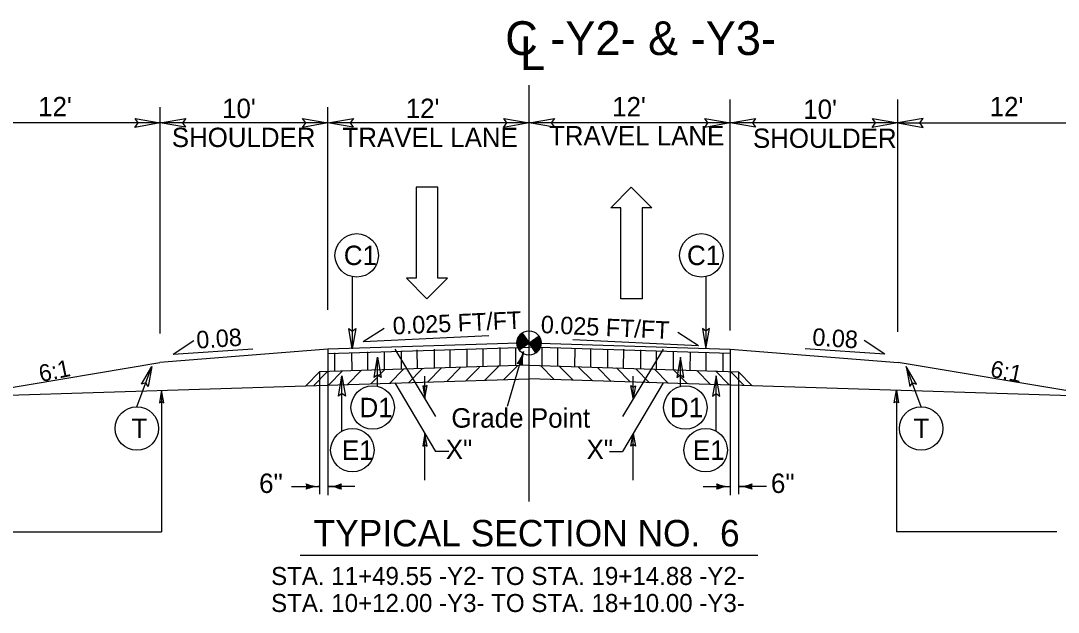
# Model space of a CAD drawing. Extents: x 2176156 to 2177167, y 76401 to 76644.
# Drawn here: x 2176967.8 to 2177029.7, y 76459.2 to 76494.4 of the extents above; entities that cross this region are included whole.
import ezdxf

# ---------------------------------------------------------------- set-up
doc = ezdxf.new("R2010")
doc.units = 0
for name, color, linetype in [('Exist Building', 7, 'Continuous'), ('Exist Building Metal Canopy', 7, 'Continuous'), ('Exist Roads Change in Surface', 7, 'Continuous'), ('Exist Roads Curbs', 7, 'Continuous'), ('Exist Roads EOP Other', 7, 'Continuous'), ('Exist Roads Soil', 7, 'Continuous'), ('Exist Structure Minor Culvert Topo', 7, 'Continuous'), ('Exist Structure Minor Drop Inlet', 7, 'Continuous'), ('Exist Utilities Other Pole CELL', 7, 'Continuous'), ('Exist Vegetation Woods Line', 7, 'Continuous'), ('Model Boundary Lines Text', 7, 'Continuous'), ('Old_Level_1', 7, 'Continuous'), ('Old_Level_3', 7, 'Continuous'), ('Prop North Arrow NAD83 for Plan Sheets CELL', 7, 'Continuous')]:
    doc.layers.add(name, color=color, linetype=linetype)

msp = doc.modelspace()

# ---------------------------------------------------------------- linework, layer by layer
at = {"layer": 'Exist Building'}
for p, q in [((2176998.106, 76473.085), (2176998.106, 76475.223)), ((2176998.106, 76473.085), (2176998.106, 76475.223)), ((2176963.901, 76472.018), (2176998.106, 76473.085)), ((2177032.311, 76472.018), (2176998.106, 76473.085))]:
    msp.add_line(p, q, dxfattribs=at)
at = {"layer": 'Exist Roads Change in Surface'}
for p, q in [((2176997.694, 76475.815), (2176998.106, 76475.223)), ((2176998.106, 76475.223), (2176998.698, 76475.635)), ((2176997.513, 76474.813), (2176998.106, 76475.223)), ((2176998.106, 76475.223), (2176997.513, 76474.813)), ((2176998.518, 76474.632), (2176998.106, 76475.223))]:
    msp.add_line(p, q, dxfattribs=at)
for points in [[(2176997.82, 76475.635), (2176997.394, 76475.338)], [(2176997.811, 76475.647), (2176997.397, 76475.359)], [(2176997.803, 76475.659), (2176997.402, 76475.38)], [(2176997.795, 76475.67), (2176997.407, 76475.401)], [(2176997.787, 76475.682), (2176997.413, 76475.422)], [(2176997.779, 76475.694), (2176997.42, 76475.444)], [(2176997.77, 76475.706), (2176997.427, 76475.467)], [(2176997.762, 76475.718), (2176997.436, 76475.491)], [(2176997.754, 76475.73), (2176997.446, 76475.515)], [(2176997.746, 76475.741), (2176997.459, 76475.542)], [(2176997.737, 76475.753), (2176997.473, 76475.569)], [(2176997.729, 76475.765), (2176997.49, 76475.599)], [(2176997.721, 76475.777), (2176997.509, 76475.63)], [(2176997.713, 76475.789), (2176997.536, 76475.666)], [(2176997.704, 76475.801), (2176997.57, 76475.707)], [(2176997.696, 76475.812), (2176997.632, 76475.768)], [(2176998.701, 76475.63), (2176998.701, 76475.63), (2176998.11, 76475.218)], [(2176997.861, 76475.576), (2176997.385, 76475.244)], [(2176997.869, 76475.564), (2176997.385, 76475.227)], [(2176997.853, 76475.588), (2176997.386, 76475.263)], [(2176997.877, 76475.552), (2176997.386, 76475.21)], [(2176997.886, 76475.54), (2176997.386, 76475.193)], [(2176997.894, 76475.528), (2176997.386, 76475.175)], [(2176997.844, 76475.599), (2176997.387, 76475.281)], [(2176997.902, 76475.517), (2176997.388, 76475.159)], [(2176997.836, 76475.611), (2176997.389, 76475.3)], [(2176997.91, 76475.505), (2176997.39, 76475.142)], [(2176997.828, 76475.623), (2176997.391, 76475.319)], [(2176997.918, 76475.493), (2176997.391, 76475.126)], [(2176997.927, 76475.481), (2176997.394, 76475.11)], [(2176997.935, 76475.469), (2176997.397, 76475.095)], [(2176997.943, 76475.457), (2176997.4, 76475.079)], [(2176997.951, 76475.446), (2176997.403, 76475.064)], [(2176997.96, 76475.434), (2176997.406, 76475.049)], [(2176997.968, 76475.422), (2176997.41, 76475.034)], [(2176997.976, 76475.41), (2176997.415, 76475.019)], [(2176997.984, 76475.398), (2176997.419, 76475.005)], [(2176997.993, 76475.386), (2176997.425, 76474.991)], [(2176998.001, 76475.375), (2176997.429, 76474.977)], [(2176998.009, 76475.363), (2176997.435, 76474.963)], [(2176998.017, 76475.351), (2176997.44, 76474.949)], [(2176998.026, 76475.339), (2176997.446, 76474.936)], [(2176998.034, 76475.327), (2176997.451, 76474.922)], [(2176998.042, 76475.315), (2176997.458, 76474.909)], [(2176998.05, 76475.304), (2176997.464, 76474.896)], [(2176998.058, 76475.292), (2176997.471, 76474.883)], [(2176998.067, 76475.28), (2176997.478, 76474.87)], [(2176998.075, 76475.268), (2176997.485, 76474.857)], [(2176998.083, 76475.256), (2176997.493, 76474.845)], [(2176998.091, 76475.244), (2176997.5, 76474.833)], [(2176998.1, 76475.233), (2176997.508, 76474.821), (2176997.508, 76474.821)], [(2176998.71, 76475.618), (2176998.118, 76475.206)], [(2176998.717, 76475.605), (2176998.126, 76475.194)], [(2176998.725, 76475.593), (2176998.134, 76475.183)], [(2176998.732, 76475.581), (2176998.143, 76475.171)], [(2176998.739, 76475.568), (2176998.151, 76475.159)], [(2176998.746, 76475.555), (2176998.159, 76475.147)], [(2176998.752, 76475.542), (2176998.167, 76475.135)], [(2176998.759, 76475.53), (2176998.176, 76475.123)], [(2176998.765, 76475.516), (2176998.184, 76475.112)], [(2176998.771, 76475.502), (2176998.192, 76475.1)], [(2176998.776, 76475.489), (2176998.2, 76475.088)], [(2176998.782, 76475.475), (2176998.209, 76475.076)], [(2176998.786, 76475.461), (2176998.217, 76475.064)], [(2176998.792, 76475.447), (2176998.225, 76475.052)], [(2176998.796, 76475.432), (2176998.233, 76475.041)], [(2176998.8, 76475.418), (2176998.241, 76475.029)], [(2176998.805, 76475.403), (2176998.25, 76475.017)], [(2176998.808, 76475.388), (2176998.258, 76475.005)], [(2176998.811, 76475.372), (2176998.266, 76474.993)], [(2176998.813, 76475.357), (2176998.274, 76474.981)], [(2176998.817, 76475.341), (2176998.283, 76474.97)], [(2176998.82, 76475.326), (2176998.291, 76474.958)], [(2176998.821, 76475.309), (2176998.299, 76474.946)], [(2176998.823, 76475.293), (2176998.307, 76474.934)], [(2176998.824, 76475.276), (2176998.316, 76474.922)], [(2176998.826, 76475.26), (2176998.324, 76474.91)], [(2176998.826, 76475.243), (2176998.332, 76474.899)], [(2176998.827, 76475.225), (2176998.34, 76474.887)], [(2176998.826, 76475.207), (2176998.349, 76474.875)], [(2176998.826, 76475.19), (2176998.357, 76474.863)], [(2176998.825, 76475.171), (2176998.365, 76474.851)], [(2176998.823, 76475.152), (2176998.373, 76474.839)], [(2176998.821, 76475.133), (2176998.381, 76474.828)], [(2176998.818, 76475.114), (2176998.39, 76474.816)], [(2176998.815, 76475.094), (2176998.398, 76474.804)], [(2176998.811, 76475.074), (2176998.406, 76474.792)], [(2176998.806, 76475.053), (2176998.414, 76474.78)], [(2176998.8, 76475.031), (2176998.423, 76474.768)], [(2176998.794, 76475.009), (2176998.431, 76474.757)], [(2176998.786, 76474.986), (2176998.439, 76474.745)], [(2176998.777, 76474.963), (2176998.447, 76474.733)], [(2176998.767, 76474.938), (2176998.456, 76474.721)], [(2176998.756, 76474.912), (2176998.464, 76474.709)], [(2176998.743, 76474.886), (2176998.472, 76474.697)], [(2176998.726, 76474.857), (2176998.48, 76474.686)], [(2176998.707, 76474.826), (2176998.489, 76474.674)], [(2176998.682, 76474.791), (2176998.497, 76474.662)], [(2176998.65, 76474.751), (2176998.505, 76474.65)], [(2176998.597, 76474.697), (2176998.513, 76474.638)]]:
    msp.add_lwpolyline(points, dxfattribs=at)
msp.add_circle((2176998.106, 76475.224), 0.721, dxfattribs=at)
for start, end in [(124.8249, 214.8249), (304.8249, 34.8249)]:
    msp.add_arc((2176998.106, 76475.224), 0.721, start, end, dxfattribs=at)
at = {"layer": 'Exist Roads Curbs'}
for points in [[(2176998.105, 76475.223), (2176998.106, 76475.223), (2176986.106, 76474.849), (2176986.106, 76474.599), (2176998.106, 76474.973), (2176998.106, 76474.973)], [(2176998.107, 76475.223), (2176998.106, 76475.223), (2177010.106, 76474.849), (2177010.106, 76474.599), (2176998.106, 76474.973), (2176998.106, 76474.973)]]:
    msp.add_lwpolyline(points, close=True, dxfattribs=at)
at = {"layer": 'Exist Roads EOP Other'}
for p, q in [((2176986.106, 76474.849), (2176976.071, 76474.046)), ((2177010.106, 76474.849), (2177020.141, 76474.046))]:
    msp.add_line(p, q, dxfattribs=at)
at = {"layer": 'Exist Roads Soil'}
for p, q in [((2176986.106, 76474.849), (2176986.106, 76473.517)), ((2177010.106, 76474.849), (2177010.106, 76473.517)), ((2176948.119, 76469.388), (2176976.071, 76474.046)), ((2176998.106, 76473.891), (2176985.602, 76473.501)), ((2176998.106, 76473.891), (2177010.61, 76473.501)), ((2177048.093, 76469.388), (2177020.141, 76474.046)), ((2176985.602, 76473.501), (2176984.793, 76472.669)), ((2177010.61, 76473.501), (2177011.419, 76472.669))]:
    msp.add_line(p, q, dxfattribs=at)
at = {"layer": 'Exist Structure Minor Drop Inlet'}
for p, q in [((2176991.381, 76484.516), (2176991.381, 76479.084)), ((2176992.661, 76484.516), (2176991.381, 76484.516)), ((2176992.661, 76479.084), (2176992.661, 76484.516)), ((2177002.992, 76483.294), (2177004.195, 76484.516)), ((2177004.195, 76484.516), (2177005.436, 76483.294)), ((2177003.574, 76483.294), (2177002.992, 76483.294)), ((2177003.574, 76477.862), (2177003.574, 76483.294)), ((2177005.436, 76483.294), (2177004.854, 76483.294)), ((2177004.854, 76483.294), (2177004.854, 76477.862)), ((2176991.381, 76479.084), (2176990.799, 76479.084)), ((2176990.799, 76479.084), (2176992.002, 76477.862)), ((2176992.002, 76477.862), (2176993.243, 76479.084)), ((2176993.243, 76479.084), (2176992.661, 76479.084)), ((2177004.854, 76477.862), (2177003.574, 76477.862))]:
    msp.add_line(p, q, dxfattribs=at)
at = {"layer": 'Exist Utilities Other Pole CELL'}
for p, q in [((2176988.212, 76475.316), (2176989.453, 76476.112)), ((2176988.212, 76475.316), (2176995.711, 76475.666)), ((2177008.22, 76475.055), (2177006.979, 76475.85)), ((2176976.878, 76474.55), (2176978.103, 76475.369)), ((2177008.22, 76475.055), (2177000.721, 76475.404)), ((2177019.334, 76474.55), (2177018.109, 76475.369)), ((2176976.878, 76474.55), (2176981.624, 76474.863)), ((2177019.334, 76474.55), (2177014.588, 76474.863))]:
    msp.add_line(p, q, dxfattribs=at)
at = {"layer": 'Model Boundary Lines Text'}
for p, q in [((2176986.525, 76473.532), (2176986.523, 76474.623)), ((2176987.543, 76473.562), (2176987.54, 76474.661)), ((2176988.483, 76473.585), (2176988.481, 76474.694)), ((2176989.484, 76473.623), (2176989.481, 76474.715)), ((2176990.501, 76473.653), (2176990.499, 76474.753)), ((2176991.442, 76473.677), (2176991.44, 76474.816)), ((2176992.46, 76473.712), (2176992.458, 76474.854)), ((2176993.404, 76473.748), (2176993.402, 76474.816)), ((2176994.421, 76473.777), (2176994.419, 76474.854)), ((2176995.365, 76473.804), (2176995.363, 76474.892)), ((2176996.382, 76473.838), (2176996.38, 76474.944)), ((2176997.323, 76473.868), (2176997.32, 76474.959)), ((2176998.89, 76473.868), (2176998.892, 76474.959)), ((2176999.83, 76473.838), (2176999.832, 76474.944)), ((2177000.847, 76473.804), (2177000.849, 76474.892)), ((2177001.791, 76473.777), (2177001.793, 76474.854)), ((2177002.808, 76473.748), (2177002.81, 76474.816)), ((2177003.752, 76473.712), (2177003.754, 76474.854)), ((2177004.77, 76473.677), (2177004.772, 76474.816)), ((2177005.711, 76473.653), (2177005.713, 76474.753)), ((2177006.728, 76473.623), (2177006.731, 76474.715)), ((2177007.729, 76473.585), (2177007.732, 76474.694)), ((2177008.669, 76473.562), (2177008.672, 76474.661)), ((2177009.687, 76473.532), (2177009.689, 76474.623)), ((2176994.328, 76472.953), (2176995.149, 76473.784)), ((2176995.477, 76473.003), (2176996.301, 76473.838)), ((2176996.602, 76473.032), (2176997.429, 76473.869)), ((2176999.61, 76473.032), (2176998.783, 76473.869)), ((2177000.735, 76473.003), (2176999.911, 76473.838)), ((2177001.884, 76472.953), (2177001.063, 76473.784)), ((2176985.264, 76472.69), (2176986.078, 76473.513)), ((2176986.157, 76472.723), (2176986.979, 76473.555)), ((2176987.276, 76472.745), (2176988.098, 76473.577)), ((2176988.659, 76472.785), (2176989.481, 76473.618)), ((2176989.797, 76472.827), (2176990.621, 76473.661)), ((2176990.916, 76472.847), (2176991.738, 76473.68)), ((2176992.065, 76472.893), (2176992.891, 76473.729)), ((2176993.205, 76472.926), (2176994.024, 76473.756)), ((2177003.007, 76472.926), (2177002.188, 76473.756)), ((2177004.147, 76472.893), (2177003.321, 76473.729)), ((2177005.296, 76472.847), (2177004.474, 76473.68)), ((2177006.415, 76472.827), (2177005.591, 76473.661)), ((2177007.553, 76472.785), (2177006.731, 76473.618)), ((2177008.936, 76472.745), (2177008.114, 76473.577)), ((2177010.055, 76472.723), (2177009.233, 76473.555)), ((2177010.948, 76472.69), (2177010.134, 76473.513)), ((2176984.445, 76462.555), (2177011.767, 76462.555))]:
    msp.add_line(p, q, dxfattribs=at)
at = {"layer": 'Old_Level_1'}
for points in [[(2176974.596, 76488.614), (2176976.106, 76488.354), (2176974.588, 76488.086), (2176974.781, 76488.354)], [(2176977.616, 76488.094), (2176976.106, 76488.354), (2176977.624, 76488.622), (2176977.431, 76488.354)], [(2176984.596, 76488.614), (2176986.106, 76488.354), (2176984.588, 76488.086), (2176984.781, 76488.354)], [(2176987.616, 76488.094), (2176986.106, 76488.354), (2176987.624, 76488.622), (2176987.431, 76488.354)], [(2176996.596, 76488.614), (2176998.106, 76488.354), (2176996.588, 76488.086), (2176996.781, 76488.354)], [(2176999.616, 76488.094), (2176998.106, 76488.354), (2176999.624, 76488.622), (2176999.431, 76488.354)], [(2177008.596, 76488.614), (2177010.106, 76488.354), (2177008.588, 76488.086), (2177008.781, 76488.354)], [(2177011.616, 76488.094), (2177010.106, 76488.354), (2177011.624, 76488.622), (2177011.431, 76488.354)], [(2177018.596, 76488.614), (2177020.106, 76488.354), (2177018.588, 76488.086), (2177018.781, 76488.354)], [(2177021.616, 76488.614), (2177020.106, 76488.354), (2177021.624, 76488.086), (2177021.431, 76488.354)], [(2176991.762, 76472.673), (2176991.894, 76471.918), (2176992.026, 76472.678), (2176991.892, 76472.581)], [(2177004.45, 76472.673), (2177004.318, 76471.918), (2177004.186, 76472.678), (2177004.32, 76472.581)], [(2176976.316, 76471.646), (2176976.186, 76472.401), (2176976.052, 76471.642), (2176976.186, 76471.738)], [(2177019.896, 76471.646), (2177020.026, 76472.401), (2177020.16, 76471.642), (2177020.026, 76471.738)], [(2176992.027, 76469.062), (2176991.894, 76469.817), (2176991.762, 76469.057), (2176991.896, 76469.154)], [(2177004.185, 76469.062), (2177004.318, 76469.817), (2177004.45, 76469.057), (2177004.316, 76469.154)]]:
    msp.add_lwpolyline(points, close=True, dxfattribs=at)
at = {"layer": 'Old_Level_3'}
for p, q in [((2176998.106, 76485.791), (2176998.106, 76490.594)), ((2176976.106, 76475.783), (2176976.106, 76489.282)), ((2176986.106, 76477.2), (2176986.106, 76489.282)), ((2177010.106, 76475.968), (2177010.106, 76489.749)), ((2177020.106, 76475.882), (2177020.106, 76489.749)), ((2176976.106, 76488.354), (2176964.106, 76488.354)), ((2176986.106, 76488.354), (2176976.106, 76488.354)), ((2176998.106, 76488.354), (2176986.212, 76488.354)), ((2177010.106, 76488.354), (2176998.106, 76488.354)), ((2177020.106, 76488.354), (2177010.106, 76488.354)), ((2177020.106, 76488.354), (2177032.106, 76488.354)), ((2176998.106, 76465.753), (2176998.106, 76485.791)), ((2176990.105, 76474.851), (2176992.531, 76470.843)), ((2177006.107, 76474.851), (2177003.681, 76470.843)), ((2176991.894, 76471.918), (2176991.894, 76473.247)), ((2177004.318, 76471.918), (2177004.318, 76473.247)), ((2176990.106, 76472.836), (2176992.531, 76468.741)), ((2177006.106, 76472.836), (2177003.681, 76468.741)), ((2176976.186, 76472.401), (2176976.186, 76463.943)), ((2177020.026, 76472.401), (2177020.026, 76463.943)), ((2176991.894, 76467.041), (2176991.894, 76469.817)), ((2177004.318, 76467.041), (2177004.318, 76469.817)), ((2176993.311, 76468.741), (2176992.531, 76468.741)), ((2177002.901, 76468.741), (2177003.681, 76468.741)), ((2176966.618, 76463.943), (2176976.186, 76463.943)), ((2177029.594, 76463.943), (2177020.026, 76463.943))]:
    msp.add_line(p, q, dxfattribs=at)
at = {"layer": 'Prop North Arrow NAD83 for Plan Sheets CELL'}
for p, q in [((2176987.558, 76479.18), (2176987.558, 76474.877)), ((2177008.654, 76479.18), (2177008.654, 76474.877)), ((2176996.826, 76471.451), (2176997.783, 76474.706)), ((2176974.711, 76471.42), (2176975.6, 76473.822)), ((2176989.067, 76472.666), (2176989.067, 76474.365)), ((2177007.145, 76472.666), (2177007.145, 76474.365)), ((2177021.501, 76471.42), (2177020.612, 76473.822)), ((2176985.606, 76473.505), (2176985.606, 76466.19)), ((2176986.106, 76473.517), (2176986.106, 76466.149)), ((2176986.937, 76469.958), (2176986.937, 76473.254)), ((2177009.276, 76469.958), (2177009.276, 76473.254)), ((2177010.106, 76473.517), (2177010.106, 76466.149)), ((2177010.606, 76473.505), (2177010.606, 76466.19)), ((2176983.939, 76466.652), (2176985.606, 76466.652)), ((2176987.706, 76466.649), (2176986.106, 76466.649)), ((2177008.506, 76466.649), (2177010.106, 76466.649)), ((2177012.273, 76466.652), (2177010.606, 76466.652))]:
    msp.add_line(p, q, dxfattribs=at)
for points in [[(2176987.765, 76476.077), (2176987.558, 76474.877), (2176987.345, 76476.083), (2176987.558, 76475.93)], [(2177008.447, 76476.077), (2177008.654, 76474.877), (2177008.867, 76476.083), (2177008.654, 76475.93)], [(2176974.99, 76472.768), (2176975.6, 76473.822), (2176975.381, 76472.616), (2176975.235, 76472.834)], [(2176988.861, 76473.165), (2176989.067, 76474.365), (2176989.281, 76473.159), (2176989.067, 76473.312)], [(2177007.351, 76473.165), (2177007.145, 76474.365), (2177006.931, 76473.159), (2177007.145, 76473.312)], [(2177021.222, 76472.768), (2177020.612, 76473.822), (2177020.831, 76472.616), (2177020.977, 76472.834)], [(2176986.73, 76472.054), (2176986.937, 76473.254), (2176987.15, 76472.047), (2176986.937, 76472.2)], [(2177009.482, 76472.054), (2177009.276, 76473.254), (2177009.062, 76472.047), (2177009.276, 76472.2)]]:
    msp.add_lwpolyline(points, close=True, dxfattribs=at)
for centre in [(2176987.823, 76480.448), (2177008.389, 76480.448), (2176988.777, 76471.37), (2177007.435, 76471.37), (2176974.711, 76470.124), (2177021.501, 76470.124), (2176987.566, 76468.825), (2177008.646, 76468.825)]:
    msp.add_circle(centre, 1.296, dxfattribs=at)
for centre, radius, start, end in [((2176995.939, 76475.222), 1.915, 320.09381, 344.37124), ((2176999.613, 76474.141), 1.915, 162.84709, 187.12452), ((2176997.442, 76473.546), 0.448, 52.84334, 94.37499), ((2176995.939, 76475.222), 1.942, 320.79834, 334.07277), ((2176995.939, 76475.222), 1.969, 321.37866, 330.22047), ((2176995.939, 76475.222), 1.995, 321.85917, 327.31211), ((2176995.939, 76475.222), 2.022, 322.25624, 324.90032), ((2176999.613, 76474.141), 2.022, 182.31801, 184.96209), ((2176999.613, 76474.141), 1.995, 179.90622, 185.35916), ((2176999.613, 76474.141), 1.969, 176.99786, 185.83967), ((2176999.613, 76474.141), 1.942, 173.14556, 186.41998), ((2176984.398, 76466.652), 0.448, 339.23433, 20.76598), ((2176985.581, 76468.567), 1.915, 246.4848, 270.76223), ((2176985.581, 76464.737), 1.915, 89.23808, 113.51551), ((2176985.581, 76468.567), 1.942, 247.18933, 260.46376), ((2176985.581, 76464.737), 1.942, 99.53654, 112.81097), ((2176985.581, 76468.567), 1.969, 247.76965, 256.61146), ((2176985.581, 76464.737), 1.969, 103.38884, 112.23066), ((2176985.581, 76468.567), 1.995, 248.25016, 253.7031), ((2176985.581, 76464.737), 1.995, 106.29721, 111.75014), ((2176985.581, 76468.567), 2.022, 248.64723, 251.29131), ((2176985.581, 76464.737), 2.022, 108.70899, 111.35308), ((2176986.132, 76468.564), 1.915, 269.23819, 293.51562), ((2176986.132, 76464.733), 1.915, 66.48492, 90.76235), ((2176986.132, 76468.564), 1.942, 279.53666, 292.81109), ((2176986.132, 76464.733), 1.942, 67.18945, 80.46388), ((2176986.132, 76468.564), 1.969, 283.38896, 292.23077), ((2176986.132, 76464.733), 1.969, 67.76976, 76.61158), ((2176986.132, 76468.564), 1.995, 286.29733, 291.75026), ((2176986.132, 76464.733), 1.995, 68.25028, 73.70321), ((2176986.132, 76468.564), 2.022, 288.70911, 291.35319), ((2176986.132, 76464.733), 2.022, 68.64734, 71.29143), ((2176987.315, 76466.648), 0.448, 159.23444, 200.7661), ((2177008.897, 76466.648), 0.448, 339.2339, 20.76556), ((2177010.081, 76468.564), 1.915, 246.48438, 270.76181), ((2177010.08, 76464.733), 1.915, 89.23765, 113.51508), ((2177010.081, 76468.564), 1.942, 247.18891, 260.46334), ((2177010.08, 76464.733), 1.942, 99.53612, 112.81055), ((2177010.081, 76468.564), 1.969, 247.76922, 256.61104), ((2177010.08, 76464.733), 1.969, 103.38842, 112.23024), ((2177010.081, 76468.564), 1.995, 248.24974, 253.70267), ((2177010.08, 76464.733), 1.995, 106.29679, 111.74972), ((2177010.081, 76468.564), 2.022, 248.64681, 251.29089), ((2177010.08, 76464.733), 2.022, 108.70857, 111.35266), ((2177010.631, 76468.567), 1.915, 269.23777, 293.5152), ((2177010.631, 76464.737), 1.915, 66.48449, 90.76193), ((2177010.631, 76468.567), 1.942, 279.53624, 292.81067), ((2177010.631, 76464.737), 1.942, 67.18903, 80.46346), ((2177010.631, 76468.567), 1.969, 283.38854, 292.23035), ((2177010.631, 76464.737), 1.969, 67.76934, 76.61116), ((2177010.631, 76468.567), 1.995, 286.2969, 291.74984), ((2177010.631, 76464.737), 1.995, 68.24986, 73.70279), ((2177010.631, 76468.567), 2.022, 288.70869, 291.35277), ((2177010.631, 76464.737), 2.022, 68.64692, 71.29101), ((2177011.815, 76466.652), 0.448, 159.23402, 200.76567)]:
    msp.add_arc(centre, radius, start, end, dxfattribs=at)

# ---------------------------------------------------------------- texts
at = {"layer": 'Exist Building Metal Canopy'}
msp.add_text('TYPICAL SECTION NO.  6', height=1.5766, rotation=0.00002, dxfattribs=at).set_placement((2176985.251, 76463.084))
at = {"layer": 'Exist Roads Curbs'}
for rotation, p in [(11.48655, (2176968.971, 76472.884)), (348.51345, (2177025.575, 76473.223))]:
    msp.add_text('6:1', height=1.0064, rotation=rotation, dxfattribs=at).set_placement(p)
at = {"layer": 'Exist Structure Minor Culvert Topo'}
for s, height, p in [("12' ", 1.1533, (2176968.817, 76488.749)), ("12'", 1.1533, (2177003.068, 76488.743)), ("12' ", 1.1533, (2177025.594, 76488.749)), ("10' ", 1.1533, (2176979.794, 76488.643)), ("12'", 1.1533, (2176990.75, 76488.643)), ("10' ", 1.1533, (2177014.47, 76488.592)), ('SHOULDER', 1.1533, (2176976.792, 76486.912)), ('TRAVEL LANE', 1.15334, (2176986.98, 76486.912)), ('TRAVEL LANE', 1.15334, (2176999.299, 76487.013)), ('SHOULDER', 1.1533, (2177011.469, 76486.862))]:
    msp.add_text(s, height=height, dxfattribs=at).set_placement(p)
at = {"layer": 'Exist Utilities Other Pole CELL'}
for s, height, rotation, p in [('0.025 FT/FT', 1.04295, 2.6676, (2176989.999, 76475.722)), ('0.025 FT/FT', 1.04295, 357.3324, (2176998.79, 76475.816)), ('0.08', 1.0429, 3.78012, (2176978.288, 76474.88)), ('0.08', 1.0429, 356.21988, (2177014.984, 76475.074))]:
    msp.add_text(s, height=height, rotation=rotation, dxfattribs=at).set_placement(p)
at = {"layer": 'Exist Vegetation Woods Line'}
for s, height, p in [('C -Y2- & -Y3- ', 2.01314, (2176996.685, 76492.404)), ('STA. 11+49.55 -Y2- TO STA. 19+14.88 -Y2-', 1.0742, (2176982.715, 76460.781)), ('STA. 10+12.00 -Y3- TO STA. 18+10.00 -Y3-', 1.0742, (2176982.715, 76459.169))]:
    msp.add_text(s, height=height, dxfattribs=at).set_placement(p)
msp.add_text('L', height=2.013, rotation=359.9469, dxfattribs=at).set_placement((2176997.563, 76491.503))
at = {"layer": 'Prop North Arrow NAD83 for Plan Sheets CELL'}
for s, rotation, p in [('C1', 0.00026, (2176987.055, 76479.868)), ('C1', 359.99974, (2177007.532, 76479.868)), ('D1', 0.00026, (2176987.991, 76470.79)), ('D1', 359.99974, (2177006.514, 76470.79)), ('Grade Point', 0.00015, (2176993.471, 76470.167)), ('T', 0.00026, (2176974.384, 76469.544)), ('T', 359.99974, (2177021.044, 76469.544)), ('E1', 0.00026, (2176986.937, 76468.245)), ('E1', 359.99974, (2177007.883, 76468.245)), ('6"', 0.00015, (2176982, 76466.271)), ('6"', 359.99985, (2177012.539, 76466.271))]:
    msp.add_text(s, height=1.16, rotation=rotation, dxfattribs=at).set_placement(p)
for p in [(2176993.141, 76468.292), (2177001.54, 76468.292)]:
    msp.add_text('X"', height=1.1533, dxfattribs=at).set_placement(p)

doc.saveas('drawing.dxf')
